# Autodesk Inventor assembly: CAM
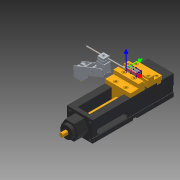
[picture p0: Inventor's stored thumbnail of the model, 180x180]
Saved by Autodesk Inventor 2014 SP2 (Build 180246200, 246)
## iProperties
Created: 2005-05
Part Number: CAM
Document SubType Name: Assembly
Designer: Administrator
Mass: 4561.57 g
Surface Area: 5905.42 cm^2
Volume: 4561.57 cm^3
Density: 1 g/cm^3
Author: Administrator
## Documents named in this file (3)
- C:\SolidCAM_Temp\PRISMA IVCAM ZWISCHENSTAND1\PRISMA IVCAM ZWISCHENSTAND1.IAM
- C:\SolidCAM_Temp\PRISMA IVCAM ZWISCHENSTAND1\DesignModel.iam
- C:\SolidCAM_Temp\PRISMA IVCAM ZWISCHENSTAND1\CAM.IPT
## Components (2 placed, 2 different names)
1. DesignModel:1 [sub-assembly]
2. CAM:1
